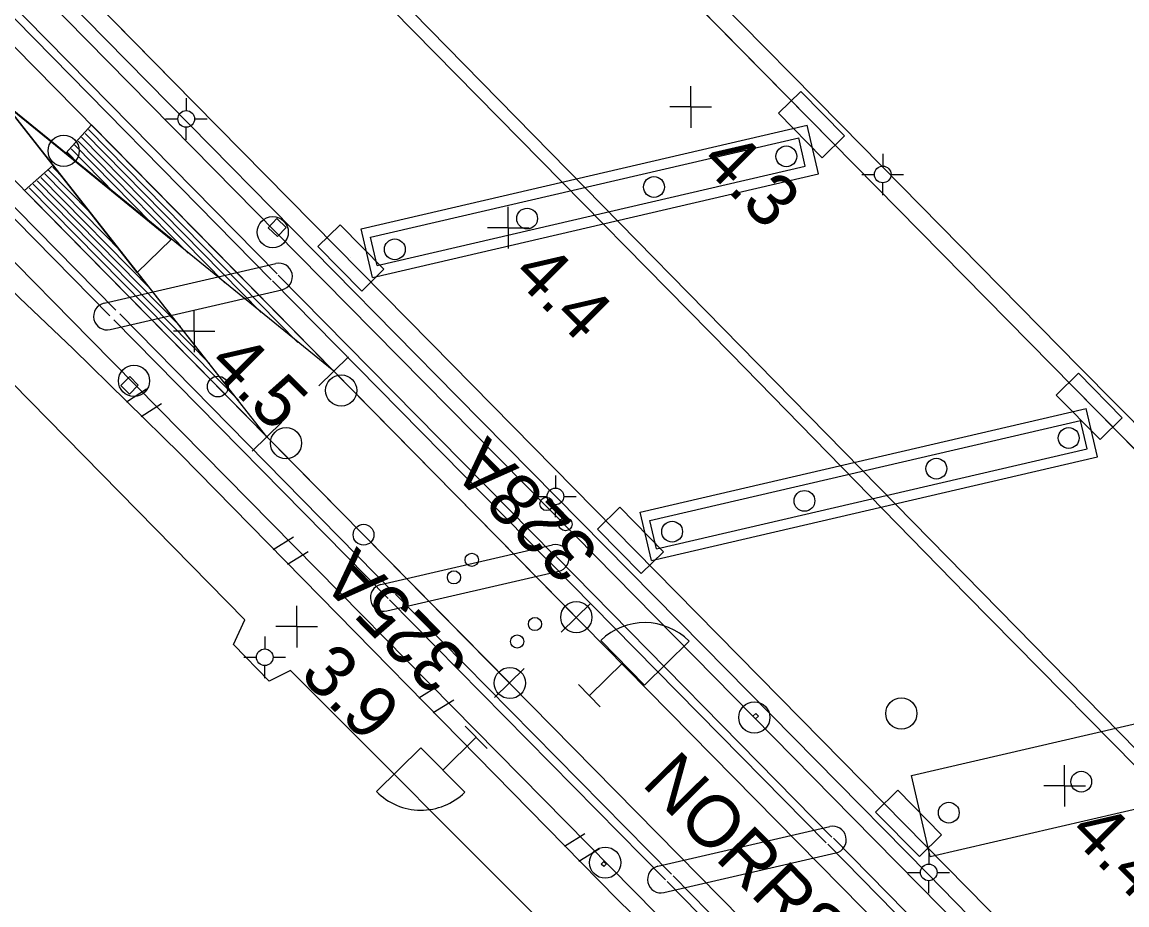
# Model space of a CAD drawing. Extents: x 1596643 to 1597288, y 13057194 to 13057957.
# Drawn here: x 1596994.5 to 1597047.6, y 13057338.6 to 13057381.1 of the extents above; entities that cross this region are included whole.
import ezdxf

# ---------------------------------------------------------------- set-up
doc = ezdxf.new("R2010")
doc.units = 0
for name, color, linetype in [('A Isolerskarv P', 7, 'Continuous'), ('A spårmitt L', 7, 'Continuous'), ('B Vxl-symbol P', 7, 'Continuous'), ('B Växel nr T', 7, 'Continuous'), ('BAS belysningsstolpe P', 7, 'Continuous'), ('BAS bro kantbalk ej def L', 7, 'Continuous'), ('BAS bropelare stöd ej def L', 7, 'Continuous'), ('BAS dagvatten brunn P', 7, 'Continuous'), ('BAS jvg-bro kantbalk L', 7, 'Continuous'), ('BAS Level 15', 7, 'Continuous'), ('BAS Level 16', 7, 'Continuous'), ('BAS Level 19', 7, 'Continuous'), ('BAS Level 29', 7, 'Continuous'), ('BAS markytetext T', 7, 'Continuous'), ('BAS staket plank lågt L', 7, 'Continuous'), ('BAS väg T', 7, 'Continuous'), ('BAS väg-bro pelare stöd L', 7, 'Continuous'), ('BAS vägbanekant L', 7, 'Continuous'), ('E ktl sträva stag fundament L', 7, 'Continuous'), ('E ktlstolpe normal centrum P', 7, 'Continuous'), ('F dvärgsignal fristående P', 7, 'Continuous')]:
    doc.layers.add(name, color=color, linetype=linetype)

msp = doc.modelspace()

# ---------------------------------------------------------------- linework, layer by layer
at = {"layer": 'A Isolerskarv P'}
for centre in [(1596996.499, 13057374.906), (1596996.499, 13057374.906), (1597009.84, 13057363.381), (1597009.84, 13057363.381), (1597007.188, 13057360.849), (1597007.188, 13057360.849), (1597021.14, 13057352.476), (1597021.14, 13057352.476), (1597017.946, 13057349.31), (1597017.946, 13057349.31)]:
    msp.add_circle(centre, 0.75, dxfattribs=at)
at = {"layer": 'A spårmitt L'}
for p, q in [((1597006.272, 13057361.158), (1596981.072, 13057393.183)), ((1597009.479, 13057364.305), (1596977.865, 13057390.027)), ((1596996.596, 13057374.797), (1596997.833, 13057376.156)), ((1596996.596, 13057374.797), (1596997.833, 13057376.156)), ((1597007.755, 13057365.695), (1596997.696, 13057375.931)), ((1597007.755, 13057365.695), (1596997.696, 13057375.931)), ((1597009.479, 13057364.305), (1596997.833, 13057376.156)), ((1597009.479, 13057364.305), (1596997.833, 13057376.156)), ((1597002.489, 13057369.984), (1596997.19, 13057375.376)), ((1597002.489, 13057369.984), (1596997.19, 13057375.376)), ((1597004.244, 13057368.555), (1596997.359, 13057375.562)), ((1597004.244, 13057368.555), (1596997.359, 13057375.562)), ((1597006, 13057367.125), (1596997.527, 13057375.747)), ((1597006, 13057367.125), (1596997.527, 13057375.747)), ((1597009.479, 13057364.305), (1596996.596, 13057374.797)), ((1597009.479, 13057364.305), (1596996.596, 13057374.797)), ((1596997.223, 13057374.273), (1596996.685, 13057374.821)), ((1596997.223, 13057374.273), (1596996.685, 13057374.821)), ((1596998.978, 13057372.843), (1596996.853, 13057375.006)), ((1596998.978, 13057372.843), (1596996.853, 13057375.006)), ((1597000.734, 13057371.414), (1596997.022, 13057375.191)), ((1597000.734, 13057371.414), (1596997.022, 13057375.191)), ((1596995.997, 13057374.215), (1596994.618, 13057373)), ((1596995.997, 13057374.215), (1596994.618, 13057373)), ((1596999.31, 13057370.021), (1596995.596, 13057373.796)), ((1596999.31, 13057370.021), (1596995.596, 13057373.796)), ((1596997.764, 13057371.949), (1596995.774, 13057373.971)), ((1596997.764, 13057371.949), (1596995.774, 13057373.971)), ((1596996.51, 13057373.579), (1596995.972, 13057374.126)), ((1596996.51, 13057373.579), (1596995.972, 13057374.126)), ((1597006.272, 13057361.158), (1596995.997, 13057374.215)), ((1597006.272, 13057361.158), (1596995.997, 13057374.215)), ((1597003.511, 13057364.684), (1596995.032, 13057373.299)), ((1597003.511, 13057364.684), (1596995.032, 13057373.299)), ((1597002.111, 13057366.463), (1596995.22, 13057373.465)), ((1597002.111, 13057366.463), (1596995.22, 13057373.465)), ((1597000.71, 13057368.242), (1596995.408, 13057373.63)), ((1597000.71, 13057368.242), (1596995.408, 13057373.63)), ((1597006.272, 13057361.158), (1596994.618, 13057373)), ((1597006.272, 13057361.158), (1596994.618, 13057373)), ((1597004.911, 13057362.905), (1596994.844, 13057373.133)), ((1597004.911, 13057362.905), (1596994.844, 13057373.133)), ((1597010.192, 13057365.006), (1597008.766, 13057363.604)), ((1597010.192, 13057365.006), (1597008.766, 13057363.604)), ((1597021.125, 13057352.454), (1597009.479, 13057364.305)), ((1597021.125, 13057352.454), (1597009.479, 13057364.305)), ((1597006.985, 13057361.859), (1597005.559, 13057360.457)), ((1597006.985, 13057361.859), (1597005.559, 13057360.457)), ((1597017.926, 13057349.316), (1597006.272, 13057361.158)), ((1597017.926, 13057349.316), (1597006.272, 13057361.158)), ((1597021.838, 13057353.155), (1597020.411, 13057351.753)), ((1597021.838, 13057353.155), (1597020.411, 13057351.753)), ((1597017.214, 13057348.614), (1597018.639, 13057350.017)), ((1597017.214, 13057348.614), (1597018.639, 13057350.017))]:
    msp.add_line(p, q, dxfattribs=at)
for points in [[(1596887.988, 13057492.75), (1596889.66, 13057490.516), (1596900.094, 13057476.776), (1596906.53, 13057469.464), (1596928.328, 13057446.663), (1596936.899, 13057437.942), (1596957.336, 13057417.351), (1597001.928, 13057371.989), (1597034.879, 13057338.506), (1597063.764, 13057309.15)], [(1596933.802, 13057434.837), (1596974.458, 13057393.515), (1596978.362, 13057389.553), (1596998.703, 13057368.849), (1597057.437, 13057309.15)]]:
    msp.add_lwpolyline(points, dxfattribs=at)
at = {"layer": 'B Vxl-symbol P'}
for p, q in [((1596993.672, 13057377.17), (1597001.667, 13057370.649)), ((1597000.039, 13057369.052), (1596993.672, 13057377.17)), ((1597001.667, 13057370.649), (1597000.039, 13057369.052))]:
    msp.add_line(p, q, dxfattribs=at)
at = {"layer": 'BAS belysningsstolpe P'}
for p, q in [((1597002.389, 13057377.441), (1597002.389, 13057376.841)), ((1597002.389, 13057377.441), (1597002.389, 13057376.841)), ((1597001.389, 13057376.441), (1597001.989, 13057376.441)), ((1597001.389, 13057376.441), (1597001.989, 13057376.441)), ((1597002.788, 13057376.441), (1597003.389, 13057376.441)), ((1597002.788, 13057376.441), (1597003.389, 13057376.441)), ((1597002.389, 13057375.441), (1597002.389, 13057376.043)), ((1597002.389, 13057375.441), (1597002.389, 13057376.043)), ((1597035.868, 13057374.77), (1597035.868, 13057374.17)), ((1597035.868, 13057374.77), (1597035.868, 13057374.17)), ((1597034.868, 13057373.77), (1597035.468, 13057373.77)), ((1597034.868, 13057373.77), (1597035.468, 13057373.77)), ((1597036.267, 13057373.77), (1597036.868, 13057373.77)), ((1597036.267, 13057373.77), (1597036.868, 13057373.77)), ((1597035.868, 13057372.77), (1597035.868, 13057373.372)), ((1597035.868, 13057372.77), (1597035.868, 13057373.372)), ((1597020.136, 13057359.287), (1597020.136, 13057358.687)), ((1597020.136, 13057359.287), (1597020.136, 13057358.687)), ((1597019.136, 13057358.287), (1597019.736, 13057358.287)), ((1597019.136, 13057358.287), (1597019.736, 13057358.287)), ((1597020.136, 13057357.287), (1597020.136, 13057357.889)), ((1597020.136, 13057357.287), (1597020.136, 13057357.889)), ((1597020.535, 13057358.287), (1597021.136, 13057358.287)), ((1597020.535, 13057358.287), (1597021.136, 13057358.287)), ((1597006.164, 13057351.548), (1597006.164, 13057350.948)), ((1597006.164, 13057351.548), (1597006.164, 13057350.948)), ((1597005.164, 13057350.548), (1597005.764, 13057350.548)), ((1597005.164, 13057350.548), (1597005.764, 13057350.548)), ((1597006.563, 13057350.548), (1597007.164, 13057350.548)), ((1597006.563, 13057350.548), (1597007.164, 13057350.548)), ((1597006.164, 13057349.548), (1597006.164, 13057350.15)), ((1597006.164, 13057349.548), (1597006.164, 13057350.15)), ((1597038.078, 13057341.202), (1597038.078, 13057340.602)), ((1597038.078, 13057341.202), (1597038.078, 13057340.602)), ((1597037.078, 13057340.202), (1597037.678, 13057340.202)), ((1597037.078, 13057340.202), (1597037.678, 13057340.202)), ((1597038.078, 13057339.202), (1597038.078, 13057339.804)), ((1597038.078, 13057339.202), (1597038.078, 13057339.804)), ((1597038.477, 13057340.202), (1597039.078, 13057340.202)), ((1597038.477, 13057340.202), (1597039.078, 13057340.202))]:
    msp.add_line(p, q, dxfattribs=at)
for centre in [(1597002.389, 13057376.441), (1597002.389, 13057376.441), (1597035.868, 13057373.77), (1597035.868, 13057373.77), (1597020.136, 13057358.287), (1597020.136, 13057358.287), (1597006.164, 13057350.548), (1597006.164, 13057350.548), (1597038.078, 13057340.202), (1597038.078, 13057340.202)]:
    msp.add_circle(centre, 0.4, dxfattribs=at)
at = {"layer": 'BAS bro kantbalk ej def L'}
for p, q in [((1596980.172, 13057396.033), (1597006.764, 13057368.984)), ((1597006.479, 13057368.704), (1596979.888, 13057395.753)), ((1596998.725, 13057366.965), (1596972.262, 13057393.865)), ((1596993.879, 13057384.028), (1597007.761, 13057369.925)), ((1596999.011, 13057367.246), (1596985.788, 13057380.683)), ((1596997.782, 13057365.837), (1596984.462, 13057379.392)), ((1597007.761, 13057369.925), (1597021.096, 13057356.385)), ((1597019.804, 13057355.171), (1597006.532, 13057368.647)), ((1597006.817, 13057368.927), (1597020.088, 13057355.451)), ((1597012.376, 13057353.649), (1596999.195, 13057367.061)), ((1597012.09, 13057353.368), (1596998.91, 13057366.78)), ((1597024.97, 13057338.226), (1596997.782, 13057365.837)), ((1597021.096, 13057356.385), (1597034.414, 13057342.845)), ((1597020.171, 13057355.391), (1597033.426, 13057341.904)), ((1597033.141, 13057341.624), (1597019.886, 13057355.111)), ((1597025.707, 13057340.118), (1597012.449, 13057353.592)), ((1597025.422, 13057339.837), (1597012.163, 13057353.311)), ((1597034.414, 13057342.845), (1597047.766, 13057329.296)), ((1597046.472, 13057328.087), (1597033.221, 13057341.565)), ((1597033.505, 13057341.845), (1597046.756, 13057328.367)), ((1597038.729, 13057326.285), (1597025.511, 13057339.762)), ((1597039.015, 13057326.566), (1597025.797, 13057340.042))]:
    msp.add_line(p, q, dxfattribs=at)
msp.add_lwpolyline([(1597031.744, 13057325.449), (1597019.684, 13057337.598), (1597007.4, 13057349.92), (1597006.374, 13057349.4), (1597004.663, 13057351.16), (1597005.204, 13057352.357), (1596994.028, 13057363.747)], dxfattribs=at)
at = {"layer": 'BAS bropelare stöd ej def L'}
for p, q in [((1596998.44, 13057367.578), (1597006.699, 13057369.489)), ((1596998.729, 13057366.311), (1597006.99, 13057368.222)), ((1597011.744, 13057354.044), (1597020.003, 13057355.955)), ((1597012.033, 13057352.777), (1597020.294, 13057354.688)), ((1597025.063, 13057340.495), (1597033.322, 13057342.406)), ((1597025.352, 13057339.228), (1597033.613, 13057341.139))]:
    msp.add_line(p, q, dxfattribs=at)
for centre, start, end in [((1597006.843, 13057368.855), 283.026, 103.0257), ((1596998.587, 13057366.945), 103.026, 283.0257), ((1597020.147, 13057355.321), 283.026, 103.0257), ((1597011.891, 13057353.411), 103.026, 283.0257), ((1597033.466, 13057341.772), 283.026, 103.0257), ((1597025.21, 13057339.862), 103.026, 283.0257)]:
    msp.add_arc(centre, 0.65, start, end, dxfattribs=at)
at = {"layer": 'BAS dagvatten brunn P'}
for p, q in [((1597032.445, 13057376.169), (1597032.445, 13057376.169)), ((1597032.445, 13057376.169), (1597032.445, 13057376.169)), ((1597010.307, 13057369.758), (1597010.307, 13057369.758)), ((1597010.307, 13057369.758), (1597010.307, 13057369.758)), ((1597045.793, 13057362.616), (1597045.793, 13057362.616)), ((1597045.793, 13057362.616), (1597045.793, 13057362.616)), ((1597023.743, 13057356.169), (1597023.743, 13057356.169)), ((1597023.743, 13057356.169), (1597023.743, 13057356.169)), ((1597037.109, 13057342.56), (1597037.109, 13057342.56)), ((1597037.109, 13057342.56), (1597037.109, 13057342.56))]:
    msp.add_line(p, q, dxfattribs=at)
for points in [[(1597030.858, 13057376.712), (1597032.963, 13057374.574), (1597034.032, 13057375.626), (1597031.927, 13057377.764)], [(1597030.858, 13057376.712), (1597032.963, 13057374.574), (1597034.032, 13057375.626), (1597031.927, 13057377.764)], [(1597011.894, 13057369.215), (1597009.789, 13057371.353), (1597008.72, 13057370.301), (1597010.825, 13057368.163)], [(1597011.894, 13057369.215), (1597009.789, 13057371.353), (1597008.72, 13057370.301), (1597010.825, 13057368.163)], [(1597044.206, 13057363.159), (1597046.311, 13057361.021), (1597047.38, 13057362.073), (1597045.275, 13057364.211)], [(1597044.206, 13057363.159), (1597046.311, 13057361.021), (1597047.38, 13057362.073), (1597045.275, 13057364.211)], [(1597022.156, 13057356.712), (1597024.261, 13057354.574), (1597025.33, 13057355.626), (1597023.225, 13057357.764)], [(1597022.156, 13057356.712), (1597024.261, 13057354.574), (1597025.33, 13057355.626), (1597023.225, 13057357.764)], [(1597038.696, 13057342.017), (1597036.591, 13057344.155), (1597035.522, 13057343.103), (1597037.627, 13057340.965)], [(1597038.696, 13057342.017), (1597036.591, 13057344.155), (1597035.522, 13057343.103), (1597037.627, 13057340.965)]]:
    msp.add_lwpolyline(points, close=True, dxfattribs=at)
at = {"layer": 'BAS jvg-bro kantbalk L'}
for p, q in [((1597020.09, 13057390.148), (1597033.863, 13057376.154)), ((1596991.946, 13057386.955), (1597003.562, 13057375.151)), ((1597033.863, 13057376.154), (1597045.33, 13057364.506)), ((1597003.562, 13057375.151), (1597015.41, 13057363.092)), ((1597045.33, 13057364.506), (1597057.124, 13057352.518)), ((1597015.41, 13057363.092), (1597027.251, 13057351.078)), ((1597027.251, 13057351.078), (1597038.048, 13057340.116)), ((1597038.048, 13057340.116), (1597049.265, 13057328.698))]:
    msp.add_line(p, q, dxfattribs=at)
at = {"layer": 'BAS Level 15'}
for centre in [(1597003.91, 13057363.571), (1597003.91, 13057363.571), (1597010.915, 13057356.443), (1597010.915, 13057356.443)]:
    msp.add_circle(centre, 0.5, dxfattribs=at)
at = {"layer": 'BAS Level 16'}
for p, q in [((1597026.637, 13057377.021), (1597026.637, 13057378.021)), ((1597026.637, 13057377.021), (1597026.637, 13057378.021)), ((1597026.637, 13057377.021), (1597025.637, 13057377.021)), ((1597026.637, 13057377.021), (1597025.637, 13057377.021)), ((1597026.637, 13057377.021), (1597027.637, 13057377.021)), ((1597026.637, 13057377.021), (1597026.637, 13057376.021)), ((1597026.637, 13057377.021), (1597027.637, 13057377.021)), ((1597026.637, 13057377.021), (1597026.637, 13057376.021)), ((1597017.869, 13057371.209), (1597017.869, 13057372.209)), ((1597017.869, 13057371.209), (1597017.869, 13057372.209)), ((1597017.869, 13057371.209), (1597016.869, 13057371.209)), ((1597017.869, 13057371.209), (1597016.869, 13057371.209)), ((1597017.869, 13057371.209), (1597018.869, 13057371.209)), ((1597017.869, 13057371.209), (1597017.869, 13057370.209)), ((1597017.869, 13057371.209), (1597018.869, 13057371.209)), ((1597017.869, 13057371.209), (1597017.869, 13057370.209)), ((1597002.773, 13057366.23), (1597002.773, 13057367.23)), ((1597002.773, 13057366.23), (1597002.773, 13057367.23)), ((1597002.773, 13057366.23), (1597001.773, 13057366.23)), ((1597002.773, 13057366.23), (1597001.773, 13057366.23)), ((1597002.773, 13057366.23), (1597003.773, 13057366.23)), ((1597002.773, 13057366.23), (1597002.773, 13057365.23)), ((1597002.773, 13057366.23), (1597003.773, 13057366.23)), ((1597002.773, 13057366.23), (1597002.773, 13057365.23)), ((1597007.705, 13057352.025), (1597007.705, 13057353.025)), ((1597007.705, 13057352.025), (1597007.705, 13057353.025)), ((1597007.705, 13057352.025), (1597006.705, 13057352.025)), ((1597007.705, 13057352.025), (1597006.705, 13057352.025)), ((1597007.705, 13057352.025), (1597008.705, 13057352.025)), ((1597007.705, 13057352.025), (1597007.705, 13057351.025)), ((1597007.705, 13057352.025), (1597008.705, 13057352.025)), ((1597007.705, 13057352.025), (1597007.705, 13057351.025)), ((1597044.611, 13057344.365), (1597044.611, 13057345.365)), ((1597044.611, 13057344.365), (1597044.611, 13057345.365)), ((1597044.611, 13057344.365), (1597043.611, 13057344.365)), ((1597044.611, 13057344.365), (1597043.611, 13057344.365)), ((1597044.611, 13057344.365), (1597045.611, 13057344.365)), ((1597044.611, 13057344.365), (1597044.611, 13057343.365)), ((1597044.611, 13057344.365), (1597045.611, 13057344.365)), ((1597044.611, 13057344.365), (1597044.611, 13057343.365))]:
    msp.add_line(p, q, dxfattribs=at)
at = {"layer": 'BAS Level 19'}
for p, q in [((1596999.512, 13057362.828), (1597000.487, 13057363.459)), ((1596999.512, 13057362.828), (1597000.487, 13057363.459)), ((1597000.225, 13057362.128), (1597001.201, 13057362.758)), ((1597000.225, 13057362.128), (1597001.201, 13057362.758)), ((1597006.562, 13057355.738), (1597007.55, 13057356.349)), ((1597006.562, 13057355.738), (1597007.55, 13057356.349)), ((1597007.262, 13057355.024), (1597008.25, 13057355.635)), ((1597007.262, 13057355.024), (1597008.25, 13057355.635)), ((1597013.564, 13057348.599), (1597014.552, 13057349.21)), ((1597013.564, 13057348.599), (1597014.552, 13057349.21)), ((1597014.264, 13057347.885), (1597015.252, 13057348.496)), ((1597014.264, 13057347.885), (1597015.252, 13057348.496)), ((1597020.565, 13057341.459), (1597021.553, 13057342.07)), ((1597020.565, 13057341.459), (1597021.553, 13057342.07)), ((1597021.265, 13057340.745), (1597022.253, 13057341.356)), ((1597021.265, 13057340.745), (1597022.253, 13057341.356))]:
    msp.add_line(p, q, dxfattribs=at)
msp.add_lwpolyline([(1596996.958, 13057365.38), (1596994.369, 13057367.841), (1596974.42, 13057388.153), (1596968.373, 13057394.355)], dxfattribs=at)
at = {"layer": 'BAS Level 29'}
for centre in [(1597019.704, 13057357.925), (1597019.704, 13057357.925), (1597020.615, 13057356.948), (1597020.615, 13057356.948), (1597016.114, 13057355.234), (1597016.114, 13057355.234), (1597015.259, 13057354.392), (1597015.259, 13057354.392), (1597019.152, 13057352.147), (1597019.152, 13057352.147), (1597018.297, 13057351.305), (1597018.297, 13057351.305)]:
    msp.add_circle(centre, 0.318, dxfattribs=at)
at = {"layer": 'BAS staket plank lågt L'}
msp.add_lwpolyline([(1597039.139, 13057323.227), (1597023.086, 13057338.935), (1597002.12, 13057360.315), (1596996.958, 13057365.38)], dxfattribs=at)
at = {"layer": 'BAS väg-bro pelare stöd L'}
for p, q in [((1597010.8, 13057371.159), (1597032.228, 13057376.144)), ((1597032.772, 13057373.806), (1597032.228, 13057376.144)), ((1597011.253, 13057370.751), (1597031.829, 13057375.538)), ((1597032.146, 13057374.174), (1597031.829, 13057375.538)), ((1597011.344, 13057368.822), (1597032.772, 13057373.806)), ((1597011.57, 13057369.388), (1597032.146, 13057374.174)), ((1597011.344, 13057368.822), (1597010.8, 13057371.159)), ((1597011.57, 13057369.388), (1597011.253, 13057370.751)), ((1597024.216, 13057357.536), (1597045.644, 13057362.52)), ((1597046.187, 13057360.183), (1597045.644, 13057362.52)), ((1597024.669, 13057357.128), (1597045.37, 13057361.943)), ((1597045.687, 13057360.58), (1597045.37, 13057361.943)), ((1597024.986, 13057355.764), (1597045.687, 13057360.58)), ((1597024.759, 13057355.198), (1597046.187, 13057360.183)), ((1597024.759, 13057355.198), (1597024.216, 13057357.536)), ((1597024.986, 13057355.764), (1597024.669, 13057357.128)), ((1597037.249, 13057344.864), (1597058.621, 13057349.814)), ((1597038.155, 13057340.968), (1597059.527, 13057345.918)), ((1597038.155, 13057340.968), (1597037.249, 13057344.864))]:
    msp.add_line(p, q, dxfattribs=at)
for centre in [(1597031.234, 13057374.641), (1597024.873, 13057373.167), (1597018.776, 13057371.648), (1597012.416, 13057370.168), (1597044.806, 13057361.095), (1597038.446, 13057359.621), (1597032.104, 13057358.071), (1597025.744, 13057356.591), (1597045.409, 13057344.565), (1597039.042, 13057343.073)]:
    msp.add_circle(centre, 0.5, dxfattribs=at)
at = {"layer": 'BAS vägbanekant L'}
for p, q in [((1597002.777, 13057377.214), (1596989.414, 13057390.809)), ((1597033.433, 13057375.328), (1597020.598, 13057388.374)), ((1597014.164, 13057365.658), (1597002.777, 13057377.214)), ((1597045.037, 13057363.541), (1597033.433, 13057375.328)), ((1597025.937, 13057353.682), (1597014.164, 13057365.658)), ((1597057.184, 13057351.183), (1597045.037, 13057363.541)), ((1597037.913, 13057341.517), (1597025.937, 13057353.682)), ((1597049.171, 13057330.064), (1597037.913, 13057341.517))]:
    msp.add_line(p, q, dxfattribs=at)
for points in [[(1597133.452, 13057259.15), (1597054.729, 13057339.299), (1596995.848, 13057399.372), (1596990.433, 13057405.034), (1596987.369, 13057408.321), (1596983.644, 13057412.319), (1596981.852, 13057414.308), (1596980.193, 13057416.206), (1596978.635, 13057418.012), (1596978.187, 13057418.58), (1596977.383, 13057419.585), (1596976.059, 13057421.351), (1596974.481, 13057423.493), (1596972.433, 13057426.487), (1596969.826, 13057430.508), (1596968.373, 13057432.851)], [(1596968.373, 13057431.554), (1596968.412, 13057431.491), (1596970.968, 13057427.583), (1596973.443, 13057423.938), (1596974.798, 13057422.081), (1596976.844, 13057419.442), (1596978.382, 13057417.442), (1596980.143, 13057415.392), (1596981.65, 13057413.616), (1596983.899, 13057411.12), (1596986.841, 13057408.015), (1596993.05, 13057401.308), (1597001.071, 13057393.121), (1597017.407, 13057376.512), (1597028.562, 13057365.159), (1597039.891, 13057353.552), (1597050.384, 13057342.909), (1597065.285, 13057327.589), (1597082.629, 13057309.925), (1597099.189, 13057293.124), (1597132.621, 13057259.15)], [(1597002.777, 13057377.214), (1596989.414, 13057390.809)], [(1597033.433, 13057375.328), (1597020.598, 13057388.374)], [(1597014.164, 13057365.658), (1597002.777, 13057377.214)], [(1597045.037, 13057363.541), (1597033.433, 13057375.328)], [(1597025.937, 13057353.682), (1597014.164, 13057365.658)], [(1597056.325, 13057352.057), (1597045.037, 13057363.541)], [(1597037.913, 13057341.517), (1597025.937, 13057353.682)], [(1597037.916, 13057341.514), (1597037.913, 13057341.517)]]:
    msp.add_lwpolyline(points, dxfattribs=at)
at = {"layer": 'E ktl sträva stag fundament L'}
for points in [[(1597006.326, 13057371.206), (1597006.77, 13057370.782), (1597007.194, 13057371.226), (1597006.75, 13057371.65), (1597006.326, 13057371.206)], [(1596999.673, 13057364.048), (1597000.087, 13057363.636), (1596999.664, 13057363.211), (1596999.25, 13057363.623), (1596999.673, 13057364.048)], [(1597029.631, 13057347.724), (1597029.759, 13057347.588), (1597029.89, 13057347.711), (1597029.762, 13057347.847), (1597029.631, 13057347.724)], [(1597022.464, 13057340.733), (1597022.59, 13057340.612), (1597022.465, 13057340.482), (1597022.339, 13057340.604), (1597022.464, 13057340.733)]]:
    msp.add_lwpolyline(points, dxfattribs=at)
at = {"layer": 'E ktlstolpe normal centrum P'}
for centre in [(1597006.548, 13057370.994), (1597006.548, 13057370.994), (1596999.88, 13057363.842), (1596999.88, 13057363.842), (1597029.695, 13057347.656), (1597029.695, 13057347.656), (1597036.762, 13057347.847), (1597036.762, 13057347.847), (1597022.527, 13057340.672), (1597022.527, 13057340.672)]:
    msp.add_circle(centre, 0.75, dxfattribs=at)
at = {"layer": 'F dvärgsignal fristående P'}
for p, q in [((1597023.37, 13057350.283), (1597021.766, 13057348.705)), ((1597023.37, 13057350.283), (1597021.766, 13057348.705)), ((1597021.24, 13057349.24), (1597022.292, 13057348.17)), ((1597021.24, 13057349.24), (1597022.292, 13057348.17)), ((1597016.856, 13057346.168), (1597015.804, 13057347.238)), ((1597016.856, 13057346.168), (1597015.804, 13057347.238)), ((1597014.726, 13057345.125), (1597016.33, 13057346.703)), ((1597014.726, 13057345.125), (1597016.33, 13057346.703))]:
    msp.add_line(p, q, dxfattribs=at)
for points in [[(1597022.318, 13057351.352), (1597024.422, 13057349.214), (1597026.56, 13057351.318)], [(1597022.318, 13057351.352), (1597024.422, 13057349.214), (1597026.56, 13057351.318)], [(1597015.778, 13057344.056), (1597013.674, 13057346.194), (1597011.536, 13057344.09)], [(1597015.778, 13057344.056), (1597013.674, 13057346.194), (1597011.536, 13057344.09)]]:
    msp.add_lwpolyline(points, dxfattribs=at)
for centre, start, end in [((1597024.422, 13057349.214), 44.5333, 134.5333), ((1597024.422, 13057349.214), 44.5333, 134.5333), ((1597013.674, 13057346.194), 224.5335, 314.5335), ((1597013.674, 13057346.194), 224.5335, 314.5335)]:
    msp.add_arc(centre, 3, start, end, dxfattribs=at)

# ---------------------------------------------------------------- texts
at = {"layer": 'B Växel nr T'}
for s, height, rotation, p in [('328A', 2.5, 134.541, (1597022.33, 13057355.677)), ('325A', 2.499, 134.532, (1597016.041, 13057350.343))]:
    msp.add_text(s, height=height, rotation=rotation, dxfattribs=at).set_placement(p)
at = {"layer": 'BAS markytetext T'}
for s, p in [('4.3', (1597027.037, 13057374.308)), ('4.4', (1597017.989, 13057368.902)), ('4.5', (1597003.377, 13057364.591)), ('3.9', (1597007.786, 13057349.657)), ('4.4', (1597044.742, 13057342.039))]:
    msp.add_text(s, height=2.5, rotation=315, dxfattribs=at).set_placement(p)
at = {"layer": 'BAS väg T'}
msp.add_text('NORRSTRÖMSBRON', height=2.5, rotation=314.541, dxfattribs=at).set_placement((1597024.235, 13057344.435))

doc.saveas('drawing.dxf')
